(* Logix 5000 project; controller ModbusRouterExample vendor 1 type 14 code 96 rev 19.11; software revision 19.01 *)

TASK MainTask (continuous, watchdog 500 ms) : MainProgram

MODULES
   Local : vendor 1 type 14 code 96 (ICP 0, rev 19.11)
      EthernetBridge : vendor 1 type 12 code 200 (ICP 1, Ethernet 192.168.1.22, rev 3.1)
         MBR01 : ETHERNET-MODULE (Ethernet 192.168.1.226, rev 1.1, Output RPI 500 ms)
END_MODULES

TYPE AparianModbusMessageRequest :
STRUCT
   DestinationAddress : INT;
   Function : INT;
   Port : INT;
   RequestSize : INT;
   IPAddress : INT[4];
   RequestData : SINT[256];
END_STRUCT
END_TYPE

TYPE AparianModbusMessageResponse :
STRUCT
   Status : INT;
   ResponseLength : INT;
   Response : SINT[255];
END_STRUCT
END_TYPE

TYPE AparianModbusRouterInput :
STRUCT
   Instance : STRING;
   Status : AparianModbusRouterStatus;
   TransactionRate : DINT;
   Temperature : REAL;
   ModbusRxPacketCount : DINT;
   ModbusTxPacketCount : DINT;
   ModbusChecksumErrors : DINT;
   ModbusTimeout : DINT;
   ModbusUnspecifiedErrors : DINT;
   TagReads : DINT;
   TagWrites : DINT;
   TagConnectionFailures : DINT;
   TagErrors : DINT;
END_STRUCT
END_TYPE

TYPE AparianModbusRouterOutput :
STRUCT
   RoutingInhibited : BOOL;
END_STRUCT
END_TYPE

TYPE AparianModbusRouterStatus :
STRUCT
   ReactiveTagMode : BOOL;
   ScheduledTagMode : BOOL;
   UnscheduledMode : BOOL;
   ConfigurationValid : BOOL;
   RoutingInhibited : BOOL;
   Reserved1 : BOOL;
   Reserved2 : BOOL;
   Reserved3 : BOOL;
   ScheduledTagStatus0 : BOOL;
   ScheduledTagStatus1 : BOOL;
   ScheduledTagStatus2 : BOOL;
   ScheduledTagStatus3 : BOOL;
   ScheduledTagStatus4 : BOOL;
   ScheduledTagStatus5 : BOOL;
   ScheduledTagStatus6 : BOOL;
   ScheduledTagStatus7 : BOOL;
   ScheduledTagStatus8 : BOOL;
   ScheduledTagStatus9 : BOOL;
   ScheduledTagStatus10 : BOOL;
   ScheduledTagStatus11 : BOOL;
   ScheduledTagStatus12 : BOOL;
   ScheduledTagStatus13 : BOOL;
   ScheduledTagStatus14 : BOOL;
   ScheduledTagStatus15 : BOOL;
   ScheduledTagStatus16 : BOOL;
   ScheduledTagStatus17 : BOOL;
   ScheduledTagStatus18 : BOOL;
   ScheduledTagStatus19 : BOOL;
END_STRUCT
END_TYPE

VAR_GLOBAL   (* controller tags *)
   MBR01Input : AparianModbusRouterInput := (Instance := 'ModbusSample', Temperature := 39.5513, ModbusRxPacketCount := 3, ModbusTxPacketCount := 5);
   MBR01Output : AparianModbusRouterOutput;
   ModbusMessageRequest : AparianModbusMessageRequest := (DestinationAddress := 1, Function := 3, Port := 1, RequestSize := 4, IPAddress[0] := 192, IPAddress[1] := 168, IPAddress[2] := 1, IPAddress[3] := 219, RequestData[3] := 2);
   ModbusMessageResponse : AparianModbusMessageResponse := (ResponseLength := 5, Response[0] := 4, Response[1] := 22, Response[2] := 46);
   ModbusMSG : MESSAGE;
        MessageParameters(ServiceCode := 16#006a, LocalElement := ModbusMessageRequest, DestinationTag := ModbusMessageResponse, ...)
   SendModbusMSG : BOOL;
END_VAR

PROGRAM MainProgram   (* main routine MainRoutine *)

ROUTINE MainRoutine   (* ladder *)
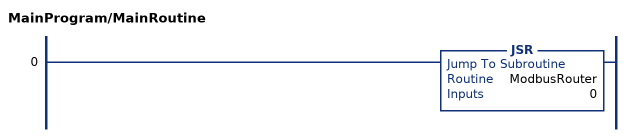
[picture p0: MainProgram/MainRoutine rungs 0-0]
   0: JSR(ModbusRouter,0);
END_ROUTINE

ROUTINE ModbusRouter   (* ladder *)
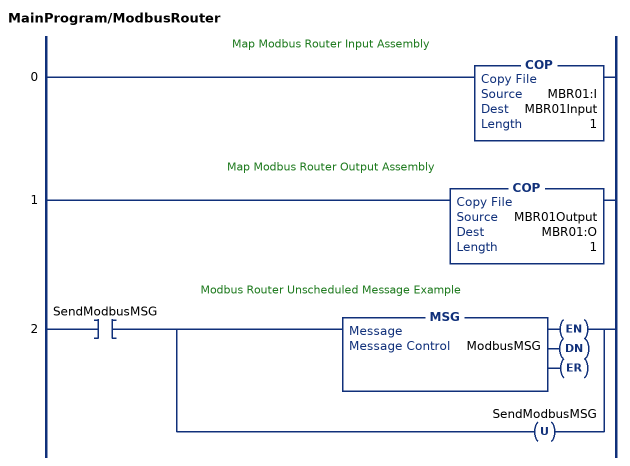
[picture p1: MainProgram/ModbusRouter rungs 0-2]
   // Map Modbus Router Input Assembly
   0: COP(MBR01:I,MBR01Input,1);
   // Map Modbus Router Output Assembly
   1: COP(MBR01Output,MBR01:O,1);
   // Modbus Router Unscheduled Message Example
   2: XIC(SendModbusMSG)[MSG(ModbusMSG) ,OTU(SendModbusMSG) ];
END_ROUTINE
END_PROGRAM
